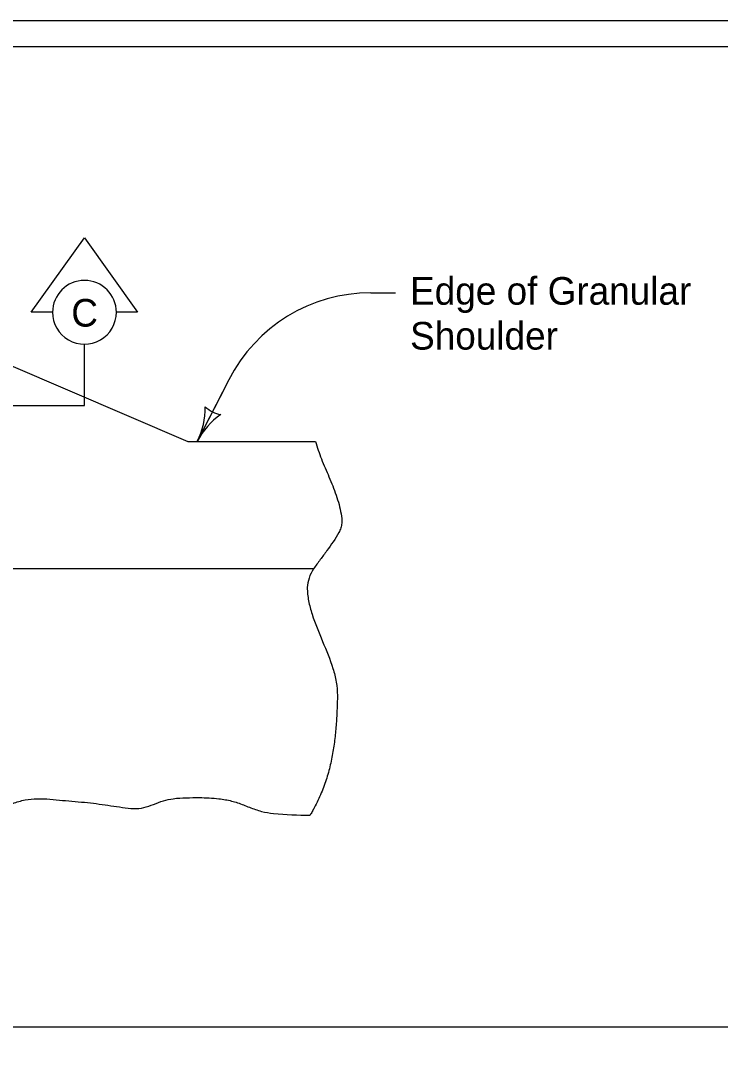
# Model space of a CAD drawing. Extents: x 9538 to 81668, y 7600 to 11751.
# Drawn here: x 11808 to 12213, y 9349 to 9944 of the extents above; entities that cross this region are included whole.
import ezdxf

# ---------------------------------------------------------------- set-up
doc = ezdxf.new("R2010")
doc.units = 0
for name, color, linetype in [('Default', 7, 'Continuous'), ('dsnStdNameDate', 7, 'Continuous'), ('dsnStdNote', 7, 'Continuous'), ('dsnStdPattern', 7, 'Continuous'), ('dsnStdShading', 7, 'Continuous'), ('dsnStdTable', 7, 'Continuous')]:
    doc.layers.add(name, color=color, linetype=linetype)

msp = doc.modelspace()

# ---------------------------------------------------------------- linework, layer by layer
at = {"layer": 'Default'}
msp.add_lwpolyline([(10132.52, 9944.02), (13267.53, 9944.02), (13267.53, 7924.02), (10132.52, 7924.02)], close=True, dxfattribs=at)
at = {"layer": 'dsnStdNameDate'}
msp.add_line((12303.1, 9361.02), (10147.52, 9361.02), dxfattribs=at)
at = {"layer": 'dsnStdNote'}
for p, q in [((12010.8, 9786.34), (12025.11, 9786.34)), ((11928.49, 9735.97), (11910.26, 9700.29))]:
    msp.add_line(p, q, dxfattribs=at)
for centre, radius, start, end in [((12010.8, 9693.91), 92.43, 90, 152.9341), ((11872.41, 9719.63), 42.5, 332.9341, 1.00659), ((11926.48, 9732.02), 16.42, 225.20075, 260.66745), ((11948.11, 9680.95), 42.5, 124.86161, 152.9341)]:
    msp.add_arc(centre, radius, start, end, dxfattribs=at)
at = {"layer": 'dsnStdPattern'}
for p, q in [((11844.89, 9721.12), (11844.89, 9756.56)), ((11756.78, 9721.12), (11844.89, 9721.12))]:
    msp.add_line(p, q, dxfattribs=at)
msp.add_lwpolyline([(11826.4, 9775.05), (11814.08, 9775.05), (11844.89, 9818.18), (11875.7, 9775.05), (11863.37, 9775.05)], dxfattribs=at)
for start, end in [(0.00083, 179.99917), (179.99917, 0.00083)]:
    msp.add_arc((11844.89, 9775.05), 18.49, start, end, dxfattribs=at)
at = {"layer": 'dsnStdShading'}
msp.add_line((10147.52, 9929.02), (13243.21, 9929.02), dxfattribs=at)
at = {"layer": 'dsnStdTable'}
for p, q in [((11800.84, 9744.89), (11904.87, 9700.29)), ((11926.51, 9732.09), (11910.26, 9700.29)), ((11904.87, 9700.29), (11978.72, 9700.29)), ((10364.45, 9626.66), (11977.72, 9626.66))]:
    msp.add_line(p, q, dxfattribs=at)
for points in [[(11978.72, 9700.29), (11982.18, 9690.15), (11986.54, 9679.77), (11990.7, 9669.14), (11992.36, 9663.73), (11993.54, 9658.26), (11993.92, 9652.88), (11993.71, 9651.51), (11993.38, 9650.15), (11992.27, 9647.57), (11985.34, 9637.07), (11983.43, 9634.43), (11981.48, 9631.81), (11979.53, 9629.19), (11977.63, 9626.52), (11974.99, 9621.14), (11973.98, 9615.65), (11974.19, 9611.8), (11974.75, 9607.94), (11976.76, 9600.17), (11982.82, 9584.51), (11988.82, 9568.79), (11990.74, 9560.94), (11991.4, 9553.1), (11991.17, 9544.51), (11990.69, 9535.86), (11989.81, 9527.13), (11989.19, 9522.79), (11988.47, 9518.46), (11986.49, 9509.66), (11983.76, 9501.06), (11980.17, 9492.41), (11978.01, 9488.11), (11976.84, 9485.97), (11975.59, 9483.83)], [(11695.88, 9487.58), (11697.88, 9487.69), (11705.46, 9488.17), (11713.02, 9488.83), (11720.57, 9489.63), (11728.11, 9490.54), (11732.85, 9491.54), (11737.54, 9492.98), (11742.21, 9494.34), (11744.56, 9494.83), (11746.92, 9495.1), (11753.46, 9495.09), (11760.05, 9494.43), (11766.64, 9493.39), (11773.15, 9492.25), (11777.16, 9491.31), (11781.14, 9490.11), (11785.12, 9488.98), (11789.12, 9488.26), (11792.67, 9488.23), (11796.22, 9488.73), (11803.32, 9490.66), (11810.46, 9492.67), (11817.63, 9493.39), (11832.17, 9492.42), (11846.71, 9491.11), (11853.43, 9490.29), (11860.14, 9489.3), (11866.83, 9488.36), (11873.51, 9487.69), (11879.27, 9488.25), (11884.94, 9490.08), (11890.61, 9492.13), (11896.32, 9493.39), (11903.82, 9493.9), (11911.43, 9494.03), (11922.81, 9493.33), (11926.55, 9492.82), (11933.57, 9491), (11940.46, 9488.43), (11947.38, 9486.06), (11954.49, 9484.83), (11975.59, 9483.83)]]:
    msp.add_spline(points, degree=3, dxfattribs=at)

# ---------------------------------------------------------------- texts
at = {"layer": 'dsnStdNote'}
for s, p in [('Edge of Granular ', (12033.54, 9779.46)), ('Shoulder', (12033.54, 9753.46))]:
    msp.add_text(s, height=16, dxfattribs=at).set_placement(p)
at = {"layer": 'dsnStdPattern'}
msp.add_text('C', height=16, dxfattribs=at).set_placement((11837.26, 9766.78))

doc.saveas('drawing.dxf')
